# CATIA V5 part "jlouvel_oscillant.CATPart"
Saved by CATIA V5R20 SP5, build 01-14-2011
Part number: Pièce 3_oscillant
Bounding box of the stored display mesh (mm): x -2.5 to 7.5, y -237.113 to 39.987, z -64.552 to 5
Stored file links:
  E:\IAO_2010\iao\IAO_MMS_Groupe2\IAO_MMS_Groupe2\OK\jlouvel\jlouvel_iao\pièces cao catia ifma\jlouvel_oscillant.CATPart
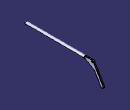
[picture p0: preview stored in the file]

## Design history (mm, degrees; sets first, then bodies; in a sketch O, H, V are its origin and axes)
Body1 (main body)
  Sketch1 on yz-plane, origin (0, 0, 0), H (0, 1, 0), V (0, 0, 1)
    line L1 (-27.1132, 5) -> (2.8868, 5)
    line L2 (2.8868, 5) -> (40.3868, -59.9519)
    line L3 (40.3868, -59.9519) -> (31.7265, -64.9519)
    line L4 (31.7265, -64.9519) -> (7.2169, -22.5)
    line L5 (7.2169, -22.5) -> (-23.094, -5)
    line L6 (-23.094, -5) -> (-27.1132, -5)
    line L7 (-27.1132, -5) -> (-27.1132, 5)
    length L7 = 10
    length L3 = 10
    length L1 = 30
    angle L2 L1 = 120
    distance L2 O = 5
    angle L5 L6 = 150
    length L5 = 35
    length L2 = 75
    horizontal: L1 H, L6 H
    perpendicularity: L3 L2
    vertical: L7 V
    parallelism: L2 L4
    symmetry: L6 L1 H
  Pad1: profile Sketch1, direction (1, 0, 0), length 5
  Sketch2 on yz-plane, origin (0, 0, 0), H (0, 1, 0), V (0, 0, 1)
    point P1 (70.0566, -121.3416)
    circle A1 centre (0, 0) radius 2
    point P2 (0, -2)
    reference projected line E1 (69.2265, -129.9038) -> (77.8868, -124.9038) from edge [face of Pad1 from Sketch1.L3 | end face of Pad1]
    distance P1 E1 = 7
    radius A1 = 2
    coincidence: A1 P2, P2 V
  Pocket1: profile Sketch2, direction (-1, 0, 0), through (limit type 6)
  Sketch3 on face of Pad1 from Sketch1.L7, origin (0, -27.1132, 0), H (1, 0, 0), V (0, 0, 1)
    circle A1 centre (2.5, 0) radius 5
    point P1 (2.5, 0)
    reference projected line E1 (0, 5) -> (5, 5) from edge [face of Pad1 from Sketch1.L7 | face of Pad1 from Sketch1.L1]
    reference projected line E2 (5, 5) -> (5, -5) from edge [face of Pad1 from Sketch1.L7 | end face of Pad1]
    radius A1 = 5
    distance P1 E1 = 5
    distance P1 E2 = 2.5
  Pad2: profile Sketch3, direction (0, -1, 0), length 210
  Fillet1: radius 3, on end face of Pad2
  Fillet2: radius 1, on end face of Pad1; start face of Pad1; edge [start face of Pad1 | face of Pad1 from Sketch1.L4]; edge [start face of Pad1 | face of Pad1 from Sketch1.L5]
  Fillet3: radius 1, on edge [face of Pad1 from Sketch1.L3 | face of Pad1 from Sketch1.L4]; edge [face of Pad1 from Sketch1.L2 | face of Pad1 from Sketch1.L3]
  Fillet4: radius 4, on edge [face of Pad1 from Sketch1.L1 | face of Pad1 from Sketch1.L2]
